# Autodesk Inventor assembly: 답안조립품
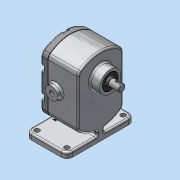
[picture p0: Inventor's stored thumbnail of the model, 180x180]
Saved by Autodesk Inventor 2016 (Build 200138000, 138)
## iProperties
Created: 2019-03
Part Number: 답안조립품
Material: 일반
Document SubType Name: Assembly
Designer: Administrator
Author: Administrator
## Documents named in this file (11)
- C:\Users\Administrator\Desktop\490307V1015\답안조립품.iam
- C:\Users\Administrator\Desktop\490307V1015\본체.ipt
- C:\Users\Administrator\Desktop\490307V1015\메인축.ipt
- C:\Users\Administrator\Desktop\490307V1015\키 6 x 6 x 18.ipt
- C:\Users\Administrator\Desktop\490307V1015\스퍼기어.ipt
- C:\Users\Administrator\Desktop\490307V1015\베어링부시.ipt
- C:\Users\Administrator\Desktop\490307V1015\서브축.ipt
- C:\Users\Administrator\Desktop\490307V1015\개스킷.ipt
- C:\Users\Administrator\Desktop\490307V1015\커버.ipt
- C:\Users\Administrator\Desktop\490307V1015\볼트 M5.ipt
- C:\Users\Administrator\Desktop\490307V1015\오일 실 16 28 7.ipt
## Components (1 placed, 1 different names)
1. 개스킷:1
